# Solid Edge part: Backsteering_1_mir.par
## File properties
Author: KULL
Template: Iso Metric Part.par
Last saved by: KULL
Revision: 2
Application: Solid Edge
Accuracy: 0,990
Username: KULL
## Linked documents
Backsteering_1.par
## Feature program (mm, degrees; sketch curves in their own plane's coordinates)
part copy "CopiedPart_1"
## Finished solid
Body 1: solid body, 239 faces, 533 edges, 296 vertices.
  Faces by surface: cylinder 104, torus 63, plane 40, blend 27, sphere 5
  Edges by curve: circle 280, line 198, ellipse 28, intersection 26, curve on surface 1
Bounding box of the edges (mm; curved faces can reach further): 28.000 x 37.345 x 39.295, from (-5, -22.1032, -19.6474) to (23, 15.242, 19.6474).
Cylindrical faces by radius (mm): R0.2 x28, R0.8 x37, R1.3 x1, R1.8 x2, R2 x4, R3 x5, R4 x12, R5 x8, R6 x3, R8 x2, R9 x2
Toroidal faces (ring radius, tube radius in mm): R1 r0.2 x2, R1 r0.8 x2, R1.2 r0.8 x2, R1.5 r0.2 x2, R1.6 r0.2 x2, R1.7 r0.4 x1, R2.2 r0.8 x4, R2.4 r0.4 x2, R3.2 r0.2 x4, R3.2 r0.8 x2, R4.2 r0.2 x12, R4.2 r0.8 x4, R4.8 r0.2 x4, R4.8 r0.8 x4, R5.2 r0.8 x4, R5.8 r0.8 x4, R8.2 r0.2 x2, R8.8 r0.2 x2, R8.8 r0.8 x2, R9.8 r0.8 x2
Spherical faces by radius (mm): R0.8 x2, R3 x1, R4 x2
Planar faces by outward normal: +x 3, +y 5, +z 2, -x 4, -y 5, -z 2, oblique 19
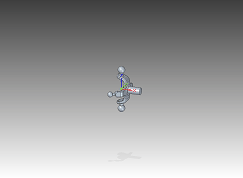
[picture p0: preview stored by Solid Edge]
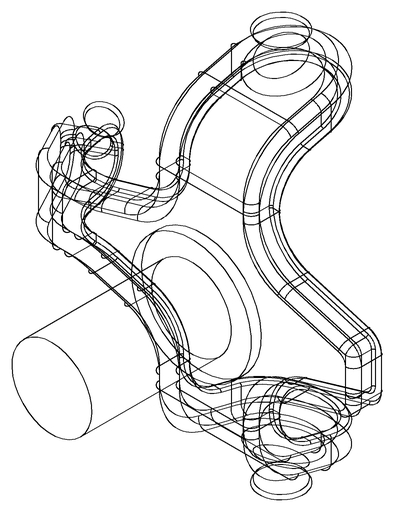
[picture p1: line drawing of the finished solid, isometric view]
